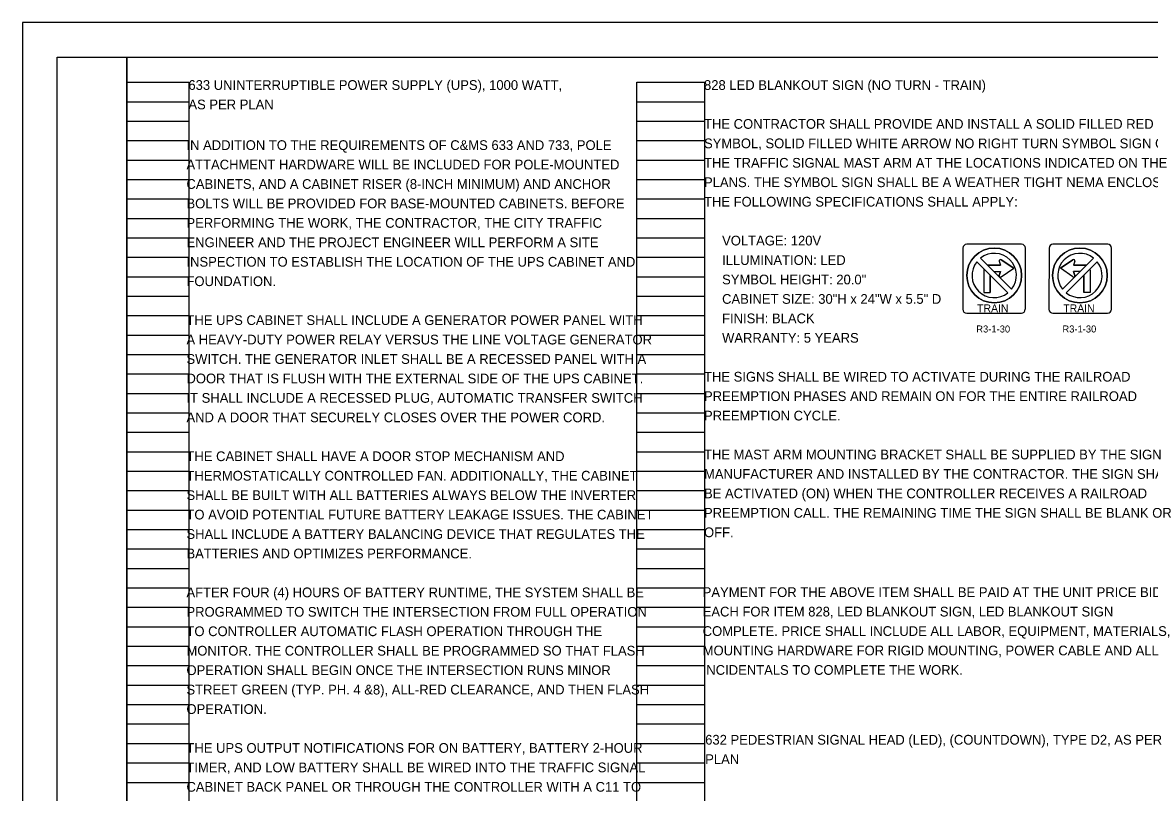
# Model space of a CAD drawing. Extents: x 0 to 34, y 0 to 22.
# Drawn here: x 0 to 16.22, y 10.91 to 22 of the extents above; entities that cross this region are included whole.
import ezdxf

# ---------------------------------------------------------------- set-up
doc = ezdxf.new("R2010")
doc.units = 0
for name, color, linetype in [('SH_Border', 7, 'Continuous'), ('SH_Cut_Line', 7, 'Continuous'), ('SH_Data', 7, 'Continuous'), ('SH_Text', 7, 'Continuous'), ('SN_P_Signs', 7, 'Continuous')]:
    doc.layers.add(name, color=color, linetype=linetype)

msp = doc.modelspace()

# ---------------------------------------------------------------- linework, layer by layer
at = {"layer": 'SH_Border'}
for points in [[(0.5, 21.5), (1.5, 21.5), (1.5, 0.5), (0.5, 0.5)], [(1.5, 21.5), (33.5, 21.5), (33.5, 0.5), (1.5, 0.5)]]:
    msp.add_lwpolyline(points, close=True, dxfattribs=at)
at = {"layer": 'SH_Cut_Line'}
msp.add_lwpolyline([(0, 0), (34, 0), (34, 22), (0, 22)], close=True, dxfattribs=at)
at = {"layer": 'SH_Data'}
for p, q in [((1.5, 0.98), (1.5, 21.14)), ((1.5, 21.14), (2.4, 21.14)), ((2.4, 0.98), (2.4, 21.14)), ((8.84, 0.98), (8.84, 21.14)), ((8.84, 21.14), (9.82, 21.14)), ((9.82, 0.98), (9.82, 21.14)), ((1.5, 20.86), (2.4, 20.86)), ((8.84, 20.86), (9.82, 20.86)), ((1.5, 20.58), (2.4, 20.58)), ((8.84, 20.58), (9.82, 20.58)), ((1.5, 20.3), (2.4, 20.3)), ((8.84, 20.3), (9.82, 20.3)), ((1.5, 20.02), (2.4, 20.02)), ((8.84, 20.02), (9.82, 20.02)), ((1.5, 19.74), (2.4, 19.74)), ((8.84, 19.74), (9.82, 19.74)), ((1.5, 19.46), (2.4, 19.46)), ((8.84, 19.46), (9.82, 19.46)), ((1.5, 19.18), (2.4, 19.18)), ((8.84, 19.18), (9.82, 19.18)), ((1.5, 18.9), (2.4, 18.9)), ((8.84, 18.9), (9.82, 18.9)), ((1.5, 18.62), (2.4, 18.62)), ((8.84, 18.62), (9.82, 18.62)), ((13.908, 18.508), (14.073, 18.508)), ((14.056, 18.563), (14.073, 18.508)), ((14.085, 18.584), (14.264, 18.461)), ((15.114, 18.584), (14.935, 18.461)), ((15.143, 18.563), (15.125, 18.508)), ((15.291, 18.508), (15.125, 18.508)), ((1.5, 18.34), (2.4, 18.34)), ((8.84, 18.34), (9.82, 18.34)), ((13.833, 18.433), (13.833, 18.114)), ((13.926, 18.361), (13.926, 18.114)), ((13.979, 18.414), (14.073, 18.414)), ((14.056, 18.358), (14.073, 18.414)), ((14.085, 18.337), (14.264, 18.461)), ((15.114, 18.337), (14.935, 18.461)), ((15.219, 18.414), (15.125, 18.414)), ((15.143, 18.358), (15.125, 18.414)), ((15.272, 18.361), (15.272, 18.114)), ((15.366, 18.433), (15.366, 18.114)), ((1.5, 18.06), (2.4, 18.06)), ((8.84, 18.06), (9.82, 18.06)), ((13.833, 18.114), (13.926, 18.114)), ((15.366, 18.114), (15.272, 18.114)), ((1.5, 17.78), (2.4, 17.78)), ((8.84, 17.78), (9.82, 17.78)), ((1.5, 17.5), (2.4, 17.5)), ((8.84, 17.5), (9.82, 17.5)), ((1.5, 17.22), (2.4, 17.22)), ((8.84, 17.22), (9.82, 17.22)), ((1.5, 16.94), (2.4, 16.94)), ((8.84, 16.94), (9.82, 16.94)), ((1.5, 16.66), (2.4, 16.66)), ((8.84, 16.66), (9.82, 16.66)), ((1.5, 16.38), (2.4, 16.38)), ((8.84, 16.38), (9.82, 16.38)), ((1.5, 16.1), (2.4, 16.1)), ((8.84, 16.1), (9.82, 16.1)), ((1.5, 15.82), (2.4, 15.82)), ((8.84, 15.82), (9.82, 15.82)), ((1.5, 15.54), (2.4, 15.54)), ((8.84, 15.54), (9.82, 15.54)), ((1.5, 15.26), (2.4, 15.26)), ((8.84, 15.26), (9.82, 15.26)), ((1.5, 14.98), (2.4, 14.98)), ((8.84, 14.98), (9.82, 14.98)), ((1.5, 14.7), (2.4, 14.7)), ((8.84, 14.7), (9.82, 14.7)), ((1.5, 14.42), (2.4, 14.42)), ((8.84, 14.42), (9.82, 14.42)), ((1.5, 14.14), (2.4, 14.14)), ((8.84, 14.14), (9.82, 14.14)), ((1.5, 13.86), (2.4, 13.86)), ((8.84, 13.86), (9.82, 13.86)), ((1.5, 13.58), (2.4, 13.58)), ((8.84, 13.58), (9.82, 13.58)), ((1.5, 13.3), (2.4, 13.3)), ((8.84, 13.3), (9.82, 13.3)), ((1.5, 13.02), (2.4, 13.02)), ((8.84, 13.02), (9.82, 13.02)), ((1.5, 12.74), (2.4, 12.74)), ((8.84, 12.74), (9.82, 12.74)), ((1.5, 12.46), (2.4, 12.46)), ((8.84, 12.46), (9.82, 12.46)), ((1.5, 12.18), (2.4, 12.18)), ((8.84, 12.18), (9.82, 12.18)), ((1.5, 11.9), (2.4, 11.9)), ((8.84, 11.9), (9.82, 11.9)), ((1.5, 11.62), (2.4, 11.62)), ((8.84, 11.62), (9.82, 11.62)), ((1.5, 11.34), (2.4, 11.34)), ((8.84, 11.34), (9.82, 11.34)), ((1.5, 11.06), (2.4, 11.06)), ((8.84, 11.06), (9.82, 11.06))]:
    msp.add_line(p, q, dxfattribs=at)
for points in [[(13.533, 18.751), (13.531, 17.871)], [(14.376, 18.808), (13.589, 18.808)], [(14.431, 17.871), (14.433, 18.751)], [(14.772, 18.751), (14.771, 17.871)], [(15.616, 18.808), (14.829, 18.808)], [(15.671, 17.871), (15.672, 18.751)], [(13.888, 18.505), (13.979, 18.414), (14.073, 18.414), (14.056, 18.358)], [(14.056, 18.563), (14.073, 18.508), (13.908, 18.508)], [(14.085, 18.337), (14.264, 18.461), (14.085, 18.584)], [(15.114, 18.337), (14.935, 18.461), (15.114, 18.584)], [(15.143, 18.563), (15.125, 18.508), (15.291, 18.508)], [(15.31, 18.505), (15.219, 18.414), (15.125, 18.414), (15.143, 18.358)], [(13.833, 18.433), (13.833, 18.114), (13.926, 18.114), (13.926, 18.361)], [(13.926, 18.361), (13.835, 18.452)], [(15.272, 18.361), (15.363, 18.452)], [(15.366, 18.433), (15.366, 18.114), (15.272, 18.114), (15.272, 18.361)], [(13.587, 17.814), (14.374, 17.814)], [(14.827, 17.814), (15.614, 17.814)]]:
    msp.add_lwpolyline(points, dxfattribs=at)
for centre, radius, start, end in [((13.589, 18.751), 0.0562, 90, 180), ((14.376, 18.751), 0.0562, 360, 90), ((14.829, 18.751), 0.0562, 90, 180), ((15.616, 18.751), 0.0562, 360, 90), ((13.908, 18.433), 0.075, 90, 105), ((13.908, 18.433), 0.075, 90, 105), ((14.074, 18.569), 0.0188, 55.4837, 197.3618), ((14.074, 18.569), 0.0188, 55.4837, 197.3618), ((15.125, 18.569), 0.0188, 342.6382, 124.5163), ((15.125, 18.569), 0.0188, 342.6382, 124.5163), ((15.291, 18.433), 0.075, 75, 90), ((15.291, 18.433), 0.075, 75, 90), ((13.908, 18.433), 0.075, 165, 180), ((13.908, 18.433), 0.075, 165, 180), ((14.074, 18.353), 0.0188, 162.6382, 304.5163), ((14.074, 18.353), 0.0188, 162.6382, 304.5163), ((15.125, 18.353), 0.0188, 235.4837, 17.3618), ((15.125, 18.353), 0.0188, 235.4837, 17.3618), ((15.291, 18.433), 0.075, 0, 15), ((15.291, 18.433), 0.075, 0, 15), ((13.587, 17.871), 0.0562, 180, 270), ((14.374, 17.871), 0.0563, 270, 360), ((14.827, 17.871), 0.0562, 180, 270), ((15.614, 17.871), 0.0563, 270, 360)]:
    msp.add_arc(centre, radius, start, end, dxfattribs=at)
at = {"layer": 'SN_P_Signs'}
for p, q in [((13.732, 18.555), (14.18, 18.107)), ((15.466, 18.555), (15.019, 18.107))]:
    msp.add_line(p, q, dxfattribs=at)
for points in [[(13.732, 18.555), (13.835, 18.452)], [(13.888, 18.505), (13.785, 18.608)], [(14.233, 18.16), (13.979, 18.414), (13.888, 18.505)], [(14.966, 18.16), (15.219, 18.414), (15.31, 18.505)], [(15.31, 18.505), (15.413, 18.608)], [(15.466, 18.555), (15.363, 18.452)], [(13.835, 18.452), (13.926, 18.361), (14.18, 18.107)], [(15.363, 18.452), (15.272, 18.361), (15.019, 18.107)]]:
    msp.add_lwpolyline(points, dxfattribs=at)
for centre in [(13.983, 18.358), (15.216, 18.358)]:
    msp.add_circle(centre, 0.394, dxfattribs=at)
for centre, radius, start, end in [((13.983, 18.358), 0.394, 360, 180), ((13.983, 18.358), 0.319, 321.7563, 128.2437), ((13.983, 18.358), 0.319, 321.7563, 128.2437), ((15.216, 18.358), 0.394, 0, 180), ((15.216, 18.358), 0.319, 51.7563, 218.2437), ((15.216, 18.358), 0.319, 51.7563, 218.2437), ((13.983, 18.358), 0.319, 141.7563, 308.2437), ((13.983, 18.358), 0.319, 141.7563, 308.2437), ((15.216, 18.358), 0.319, 231.7563, 38.2437), ((15.216, 18.358), 0.319, 231.7563, 38.2437), ((13.983, 18.358), 0.394, 180, 360), ((15.216, 18.358), 0.394, 180, 0)]:
    msp.add_arc(centre, radius, start, end, dxfattribs=at)

# ---------------------------------------------------------------- texts
at = {"layer": 'SH_Data'}
for p in [(13.737, 17.829), (14.977, 17.829)]:
    msp.add_text('TRAIN', height=0.1125, rotation=360, dxfattribs=at).set_placement(p)
at = {"layer": 'SH_Text'}
for s, height, p in [('633 UNINTERRUPTIBLE POWER SUPPLY (UPS), 1000 WATT,', 0.14, (2.387, 21.03)), ('828 LED BLANKOUT SIGN (NO TURN - TRAIN)', 0.14, (9.807, 21.03)), ('AS PER PLAN', 0.14, (2.387, 20.75)), ('THE CONTRACTOR SHALL PROVIDE AND INSTALL A SOLID FILLED RED ', 0.14, (9.807, 20.47)), ('IN ADDITION TO THE REQUIREMENTS OF C&MS 633 AND 733, POLE ', 0.14, (2.359, 20.165)), ('SYMBOL, SOLID FILLED WHITE ARROW NO RIGHT TURN SYMBOL SIGN ON ', 0.14, (9.807, 20.19)), ('ATTACHMENT HARDWARE WILL BE INCLUDED FOR POLE-MOUNTED ', 0.14, (2.359, 19.885)), ('THE TRAFFIC SIGNAL MAST ARM AT THE LOCATIONS INDICATED ON THE ', 0.14, (9.807, 19.91)), ('CABINETS, AND A CABINET RISER (8-INCH MINIMUM) AND ANCHOR ', 0.14, (2.359, 19.605)), ('PLANS. THE SYMBOL SIGN SHALL BE A WEATHER TIGHT NEMA ENCLOSURE. ', 0.14, (9.807, 19.63)), ('BOLTS WILL BE PROVIDED FOR BASE-MOUNTED CABINETS. BEFORE ', 0.14, (2.359, 19.325)), ('THE FOLLOWING SPECIFICATIONS SHALL APPLY:', 0.14, (9.807, 19.35)), ('PERFORMING THE WORK, THE CONTRACTOR, THE CITY TRAFFIC ', 0.14, (2.359, 19.045)), ('ENGINEER AND THE PROJECT ENGINEER WILL PERFORM A SITE ', 0.14, (2.359, 18.765)), ('     VOLTAGE: 120V', 0.14, (9.807, 18.79)), ('     ILLUMINATION: LED', 0.14, (9.807, 18.51)), ('INSPECTION TO ESTABLISH THE LOCATION OF THE UPS CABINET AND ', 0.14, (2.359, 18.485)), ('FOUNDATION.', 0.14, (2.359, 18.205)), ('     SYMBOL HEIGHT: 20.0"', 0.14, (9.807, 18.23)), ('     CABINET SIZE: 30"H x 24"W x 5.5" D', 0.14, (9.807, 17.95)), ('THE UPS CABINET SHALL INCLUDE A GENERATOR POWER PANEL WITH ', 0.14, (2.359, 17.645)), ('     FINISH: BLACK', 0.14, (9.807, 17.67)), ('     WARRANTY: 5 YEARS', 0.14, (9.807, 17.39)), ('R3-1-30', 0.1008, (13.725, 17.537)), ('R3-1-30', 0.1008, (14.965, 17.537)), ('A HEAVY-DUTY POWER RELAY VERSUS THE LINE VOLTAGE GENERATOR ', 0.14, (2.359, 17.365)), ('SWITCH. THE GENERATOR INLET SHALL BE A RECESSED PANEL WITH A ', 0.14, (2.359, 17.085)), ('DOOR THAT IS FLUSH WITH THE EXTERNAL SIDE OF THE UPS CABINET. ', 0.14, (2.359, 16.805)), ('THE SIGNS SHALL BE WIRED TO ACTIVATE DURING THE RAILROAD ', 0.14, (9.807, 16.83)), ('IT SHALL INCLUDE A RECESSED PLUG, AUTOMATIC TRANSFER SWITCH ', 0.14, (2.359, 16.525)), ('PREEMPTION PHASES AND REMAIN ON FOR THE ENTIRE RAILROAD ', 0.14, (9.807, 16.55)), ('AND A DOOR THAT SECURELY CLOSES OVER THE POWER CORD.', 0.14, (2.359, 16.245)), ('PREEMPTION CYCLE.', 0.14, (9.807, 16.27)), ('THE CABINET SHALL HAVE A DOOR STOP MECHANISM AND ', 0.14, (2.359, 15.685)), ('THE MAST ARM MOUNTING BRACKET SHALL BE SUPPLIED BY THE SIGN ', 0.14, (9.807, 15.71)), ('MANUFACTURER AND INSTALLED BY THE CONTRACTOR. THE SIGN SHALL ', 0.14, (9.807, 15.43)), ('THERMOSTATICALLY CONTROLLED FAN. ADDITIONALLY, THE CABINET ', 0.14, (2.359, 15.405)), ('SHALL BE BUILT WITH ALL BATTERIES ALWAYS BELOW THE INVERTER ', 0.14, (2.359, 15.125)), ('BE ACTIVATED (ON) WHEN THE CONTROLLER RECEIVES A RAILROAD ', 0.14, (9.807, 15.15)), ('TO AVOID POTENTIAL FUTURE BATTERY LEAKAGE ISSUES. THE CABINET', 0.14, (2.359, 14.845)), ('PREEMPTION CALL. THE REMAINING TIME THE SIGN SHALL BE BLANK OR ', 0.14, (9.807, 14.87)), ('SHALL INCLUDE A BATTERY BALANCING DEVICE THAT REGULATES THE', 0.14, (2.359, 14.565)), ('OFF.', 0.14, (9.807, 14.59)), ('BATTERIES AND OPTIMIZES PERFORMANCE.', 0.14, (2.359, 14.285)), ('AFTER FOUR (4) HOURS OF BATTERY RUNTIME, THE SYSTEM SHALL BE ', 0.14, (2.359, 13.725)), ('PAYMENT FOR THE ABOVE ITEM SHALL BE PAID AT THE UNIT PRICE BID PER ', 0.14, (9.788, 13.728)), ('PROGRAMMED TO SWITCH THE INTERSECTION FROM FULL OPERATION ', 0.14, (2.359, 13.445)), ('EACH FOR ITEM 828, LED BLANKOUT SIGN, LED BLANKOUT SIGN ', 0.14, (9.788, 13.448)), ('TO CONTROLLER AUTOMATIC FLASH OPERATION THROUGH THE ', 0.14, (2.359, 13.165)), ('COMPLETE. PRICE SHALL INCLUDE ALL LABOR, EQUIPMENT, MATERIALS, ', 0.14, (9.788, 13.168)), ('MONITOR. THE CONTROLLER SHALL BE PROGRAMMED SO THAT FLASH ', 0.14, (2.359, 12.885)), ('MOUNTING HARDWARE FOR RIGID MOUNTING, POWER CABLE AND ALL ', 0.14, (9.788, 12.888)), ('OPERATION SHALL BEGIN ONCE THE INTERSECTION RUNS MINOR ', 0.14, (2.359, 12.605)), ('INCIDENTALS TO COMPLETE THE WORK.', 0.14, (9.788, 12.608)), ('STREET GREEN (TYP. PH. 4 &8), ALL-RED CLEARANCE, AND THEN FLASH ', 0.14, (2.359, 12.325)), ('OPERATION.', 0.14, (2.359, 12.045)), ('632 PEDESTRIAN SIGNAL HEAD (LED), (COUNTDOWN), TYPE D2, AS PER ', 0.14, (9.824, 11.603)), ('THE UPS OUTPUT NOTIFICATIONS FOR ON BATTERY, BATTERY 2-HOUR ', 0.14, (2.359, 11.485)), ('PLAN', 0.14, (9.824, 11.323)), ('TIMER, AND LOW BATTERY SHALL BE WIRED INTO THE TRAFFIC SIGNAL ', 0.14, (2.359, 11.205)), ('CABINET BACK PANEL OR THROUGH THE CONTROLLER WITH A C11 TO ', 0.14, (2.359, 10.925))]:
    msp.add_text(s, height=height, dxfattribs=at).set_placement(p)

doc.saveas('drawing.dxf')
